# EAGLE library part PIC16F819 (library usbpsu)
PIC MICRO (16 I/O 10bit-5ch ADC 20MHz)
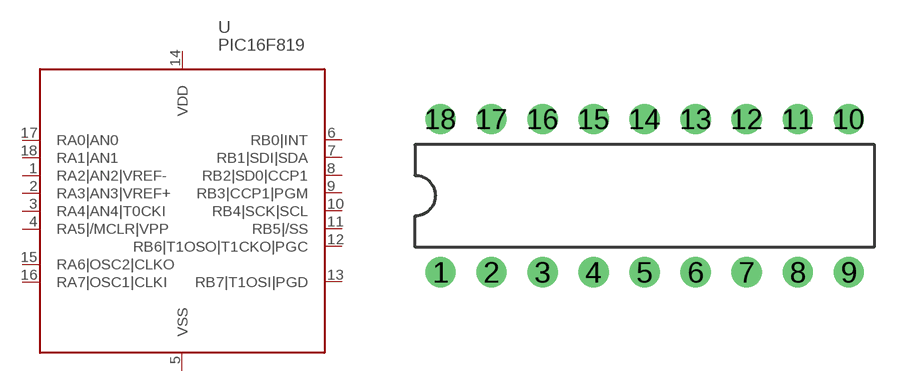
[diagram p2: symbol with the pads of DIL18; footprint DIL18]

Designator prefix -

## PIC16F819DIL18  [DIL18]
1  RA2|AN2|VREF-
2  RA3|AN3|VREF+
3  RA4|AN4|T0CKI
4  RA5|/MCLR|VPP
5  VSS  pwr
6  RB0|INT
7  RB1|SDI|SDA
8  RB2|SD0|CCP1
9  RB3|CCP1|PGM
10  RB4|SCK|SCL
11  RB5|/SS
12  RB6|T1OSO|T1CKO|PGC
13  RB7|T1OSI|PGD
14  VDD  pwr
15  RA6|OSC2|CLKO
16  RA7|OSC1|CLKI
17  RA0|AN0
18  RA1|AN1

## Footprint DIL18 (pad centres in mm)
Dual In Line Package
drill 1 round: 1 -10.16,-3.81; 2 -7.62,-3.81; 3 -5.08,-3.81; 4 -2.54,-3.81; 5 0,-3.81; 6 2.54,-3.81; 7 5.08,-3.81; 8 7.62,-3.81; 9 10.16,-3.81; 10 10.16,3.81; 11 7.62,3.81; 12 5.08,3.81; 13 2.54,3.81; 14 0,3.81; 15 -2.54,3.81; 16 -5.08,3.81; 17 -7.62,3.81; 18 -10.16,3.81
